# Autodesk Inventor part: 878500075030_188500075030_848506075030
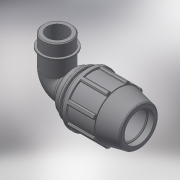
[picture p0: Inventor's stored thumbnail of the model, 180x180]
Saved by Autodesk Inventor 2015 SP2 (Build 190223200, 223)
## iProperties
Created: 2017-02
Part Number: 878500075030_188500075030_848506075030
Material: Generic
Description: PLASSON 90° ELBOW MALE ADAPTOR 75-3"
Document SubType Name: Modeling
Designer: KIM
Mass: 1366.09 g
Surface Area: 1816.46 cm^2
Volume: 1366.09 cm^3
Density: 1 g/cm^3
Appearance: Default
Author: KIM
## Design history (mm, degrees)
derived "87850.ipt"
feature "Solid1::87850.ipt"
tag "TaggingFeature1"
body "Solid1"
other parameters: "d2" = 75, "d4" = 17.25, "d5" = 51.75, "d7" = 132, "d9" = 29.57143, "d11" = 6.9, "d13" = 120 deg, "d14" = 97.5, "d15" = 12 deg, "d16" = 114.84, "d18" = 3.75, "d19" = 35 deg, "d20" = 17.5 deg, "d21" = 122.76, "d23" = 0, "d25" = 360 deg, "d27" = 2.64, "d33" = 1.5, "d42" = 76.59, "d43" = 3.96, "d46" = 2.25, "d51" = 207, "d68" = 13.8, "d73" = 87.884, "d74" = 33, "d75" = 101.0666, "d76" = 61.5188, "d77" = 36.3, "d79" = 35.1536, "d80" = 2.63652, "d83" = 0, "d84" = 0, "d91" = 99, "d93" = 137, "d94" = 87.884, "d95" = 61.5188, "d96" = 13.8, "d97" = 50 deg, "d98" = 3.45, "d99" = 111.3948, "d100" = 3.45, "d101" = 3.45, "d102" = 8.8, "d103" = 0, "d_" = 75, "E_" = 132, "A_" = 207, "l_" = 137, "l_2" = 33, "G_" = 87.884
